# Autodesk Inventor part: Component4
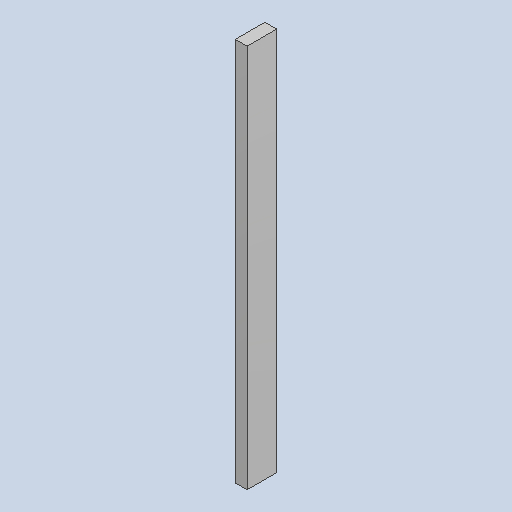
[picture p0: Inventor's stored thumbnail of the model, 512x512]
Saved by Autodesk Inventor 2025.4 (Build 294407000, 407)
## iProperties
Created: 2026-06
Part Number: Component4
Material: Generic
Document SubType Name: Modeling
Designer: AdminForWorker
Density: 1 g/cm^3
Appearance: Default
Title: Component4
Author: AdminForWorker
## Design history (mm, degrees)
feature "Body1"
body "Solid1"
